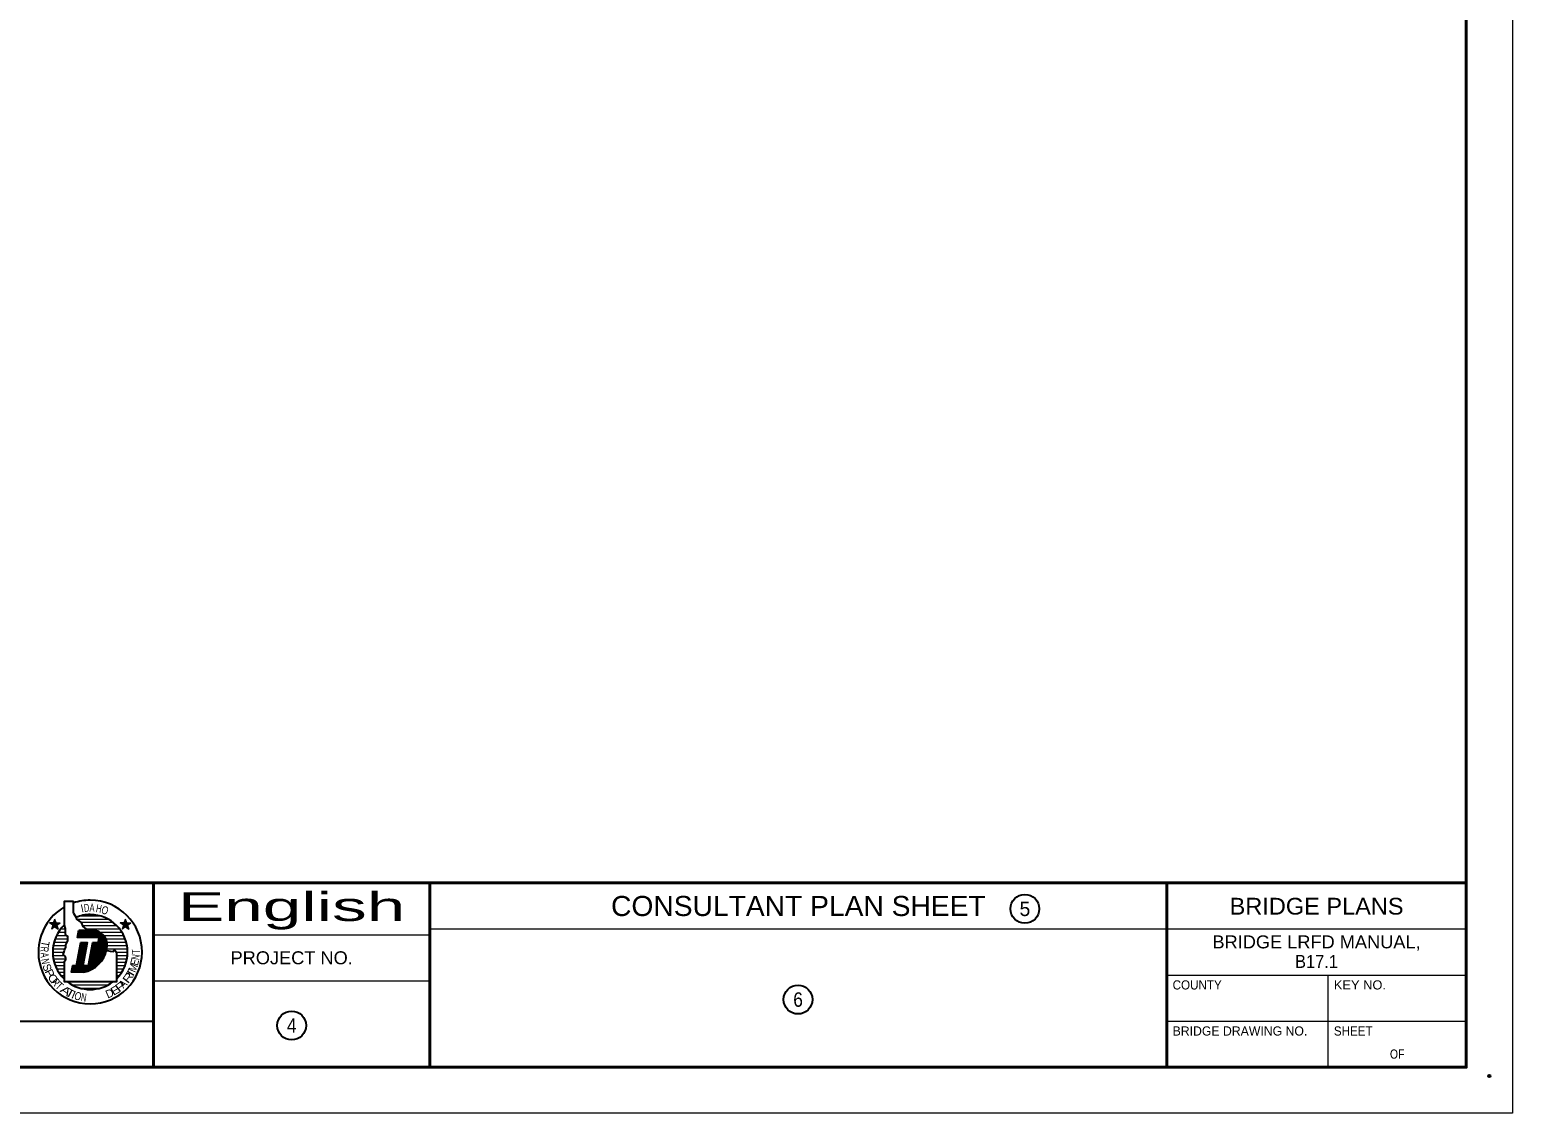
# Model space of a CAD drawing. Extents: x 0 to 34, y 0 to 23.5.
# Drawn here: x 17.91 to 34, y 0 to 11.76 of the extents above; entities that cross this region are included whole.
import ezdxf
from ezdxf.enums import TextEntityAlignment as Align

# ---------------------------------------------------------------- set-up
doc = ezdxf.new("R2010")
doc.units = 0
doc.header["$LTSCALE"] = 0.05
doc.header["$PDMODE"] = 32
doc.header["$PDSIZE"] = 0.025
doc.layers.add('49', color=7, linetype='Continuous')
doc.layers.add('50', color=7, linetype='Continuous', lineweight=13)
doc.layers.add('54', color=7, linetype='Continuous', lineweight=25)

msp = doc.modelspace()

# ---------------------------------------------------------------- linework, layer by layer
at = {"layer": '49'}
msp.add_point((33.75, 0.40625), dxfattribs=at)
at = {"layer": '50', "lineweight": 40}
for p, q in [((1.5, 2.5), (19.25, 2.5)), ((19.25, 0.5), (19.25, 2.5)), ((19.25, 2.5), (33.5, 2.5)), ((22.25, 0.5), (22.25, 2.5)), ((30.25, 0.5), (30.25, 2.5))]:
    msp.add_line(p, q, dxfattribs=at)
at = {"layer": '50', "lineweight": 25}
for p, q in [((18.38312, 2.17313), (18.38312, 2.30313)), ((18.43938, 1.90688), (18.45375, 1.98563)), ((18.44063, 1.98563), (18.6125, 1.98563)), ((18.455, 1.90688), (18.47, 1.98563)), ((18.47125, 1.90688), (18.48563, 1.98563)), ((18.48688, 1.90688), (18.50188, 1.98563)), ((18.5025, 1.90688), (18.5175, 1.98563)), ((18.51875, 1.90688), (18.53313, 1.98563)), ((18.53438, 1.90688), (18.54938, 1.98563)), ((18.55063, 1.90688), (18.565, 1.98563)), ((18.56625, 1.90688), (18.58125, 1.98563)), ((18.5825, 1.90688), (18.59688, 1.98563)), ((18.59812, 1.90688), (18.61313, 1.98563)), ((18.59938, 1.57438), (18.67188, 1.96188)), ((18.61375, 1.90688), (18.62813, 1.98125)), ((18.6175, 1.58563), (18.68625, 1.95188)), ((18.63, 1.90688), (18.64313, 1.97688)), ((18.63625, 1.60063), (18.69937, 1.93875)), ((18.64563, 1.90688), (18.6575, 1.97)), ((18.41625, 1.53188), (18.47687, 1.855)), ((18.4325, 1.53188), (18.49313, 1.855)), ((18.44813, 1.53188), (18.50875, 1.855)), ((18.46438, 1.53188), (18.525, 1.855)), ((18.54688, 1.5475), (18.60438, 1.855)), ((18.56375, 1.555), (18.62, 1.855)), ((18.58125, 1.56313), (18.63625, 1.855)), ((18.65563, 1.61875), (18.7125, 1.92438)), ((18.67563, 1.64), (18.725, 1.90625)), ((18.69688, 1.66875), (18.73688, 1.88188)), ((18.72188, 1.7175), (18.74563, 1.845)), ((18.36875, 1.53188), (18.3825, 1.605)), ((18.385, 1.53188), (18.39875, 1.605)), ((18.40063, 1.53188), (18.41437, 1.605)), ((18.48, 1.53188), (18.49375, 1.605)), ((18.49625, 1.5325), (18.51, 1.605)), ((18.51313, 1.53687), (18.52563, 1.605)), ((18.53, 1.54188), (18.54125, 1.605)), ((14, 1), (19.25, 1))]:
    msp.add_line(p, q, dxfattribs=at)
at = {"layer": '50'}
for p, q in [((18.16563, 2.06563), (18.17938, 2.10688)), ((18.17938, 2.02375), (18.17938, 2.10688)), ((18.19313, 2.06563), (18.17938, 2.10688)), ((18.41688, 2.10813), (18.75062, 2.10813)), ((18.465, 2.14438), (18.65813, 2.14438)), ((18.93188, 2.06563), (18.94562, 2.10688)), ((18.94562, 2.02375), (18.94562, 2.10688)), ((18.95938, 2.06563), (18.94562, 2.10688)), ((18.20125, 2.04), (18.1225, 2.06563)), ((18.16563, 2.06563), (18.1225, 2.06563)), ((18.1575, 2.04), (18.1225, 2.06563)), ((18.19313, 2.06563), (18.14375, 1.99813)), ((18.1575, 2.04), (18.14375, 1.99813)), ((18.17938, 2.02375), (18.14375, 1.99813)), ((18.1575, 2.04), (18.23688, 2.06563)), ((18.16563, 2.06563), (18.215, 1.99813)), ((18.17938, 2.02375), (18.215, 1.99813)), ((18.19313, 2.06563), (18.23688, 2.06563)), ((18.20125, 2.04), (18.23688, 2.06563)), ((18.20125, 2.04), (18.215, 1.99813)), ((18.21688, 1.96438), (18.2925, 1.96438)), ((18.24188, 2.00063), (18.29375, 2.00063)), ((18.27438, 2.03625), (18.28625, 2.03625)), ((18.465, 2.0725), (18.80688, 2.0725)), ((18.47875, 2.03625), (18.85063, 2.03625)), ((18.51562, 2.00063), (18.8825, 2.00063)), ((18.66875, 1.96438), (18.9075, 1.96438)), ((18.9675, 2.04), (18.88813, 2.06563)), ((18.92375, 2.04), (18.88813, 2.06563)), ((18.93188, 2.06563), (18.88813, 2.06563)), ((18.95938, 2.06563), (18.91, 1.99813)), ((18.92375, 2.04), (18.91, 1.99813)), ((18.94562, 2.02375), (18.91, 1.99813)), ((18.92375, 2.04), (19.0025, 2.06563)), ((18.93188, 2.06563), (18.98125, 1.99813)), ((18.94562, 2.02375), (18.98125, 1.99813)), ((18.95938, 2.06563), (19.0025, 2.06563)), ((18.9675, 2.04), (19.0025, 2.06563)), ((18.9675, 2.04), (18.98125, 1.99813)), ((19.25, 1.9375), (22.25, 1.9375)), ((22.25, 2), (30.25, 2)), ((30.25, 2), (33.5, 2)), ((18.1575, 1.78438), (18.29063, 1.78438)), ((18.1625, 1.82063), (18.29813, 1.82063)), ((18.17063, 1.85625), (18.31125, 1.85625)), ((18.18125, 1.8925), (18.31875, 1.8925)), ((18.19688, 1.92813), (18.29813, 1.92813)), ((18.71, 1.92813), (18.9275, 1.92813)), ((18.7325, 1.8925), (18.94313, 1.8925)), ((18.7425, 1.78438), (18.9675, 1.78438)), ((18.74438, 1.85625), (18.95438, 1.85625)), ((18.7475, 1.82063), (18.9625, 1.82063)), ((18.15625, 1.74813), (18.2775, 1.74813)), ((18.15813, 1.7125), (18.28125, 1.7125)), ((18.16313, 1.67625), (18.29813, 1.67625)), ((18.17125, 1.64062), (18.28375, 1.64062)), ((18.845, 1.74813), (18.96875, 1.74813)), ((18.84688, 1.67625), (18.96188, 1.67625)), ((18.84688, 1.64062), (18.95375, 1.64062)), ((18.8475, 1.7125), (18.96688, 1.7125)), ((18.18375, 1.60438), (18.2825, 1.60438)), ((18.19937, 1.56812), (18.2825, 1.56812)), ((18.22, 1.5325), (18.28313, 1.5325)), ((18.24563, 1.49625), (18.2825, 1.49625)), ((18.2775, 1.46063), (18.28375, 1.46063)), ((18.84688, 1.60438), (18.94125, 1.60438)), ((18.84688, 1.56812), (18.925, 1.56812)), ((18.84688, 1.5325), (18.905, 1.5325)), ((18.84688, 1.49625), (18.88, 1.49625)), ((30.25, 1.5), (33.5, 1.5)), ((32, 0.5), (32, 1.5)), ((18.75062, 1.39125), (18.37188, 1.39125)), ((18.65875, 1.35563), (18.4675, 1.35563)), ((19.25, 1.4375), (22.25, 1.4375)), ((30.25, 1), (33.5, 1))]:
    msp.add_line(p, q, dxfattribs=at)
msp.add_lwpolyline([(0, 22), (34, 22), (34, 0), (0, 0)], close=True, dxfattribs=at)
at = {"layer": '50', "lineweight": 40}
msp.add_lwpolyline([(1.5, 21.5), (33.5, 21.5), (33.5, 0.5), (1.5, 0.5)], close=True, dxfattribs=at)
at = {"layer": '50', "lineweight": 25}
for points in [[(18.74063, 1.7775), (18.74813, 1.76625), (18.77938, 1.76125), (18.81063, 1.75625), (18.82625, 1.77688), (18.84688, 1.74563), (18.84688, 1.4275), (18.28438, 1.4275), (18.28438, 1.65188), (18.3, 1.6675), (18.3, 1.68313), (18.29438, 1.69375), (18.28438, 1.70938), (18.26875, 1.725), (18.27875, 1.75063), (18.28438, 1.77188), (18.3, 1.80313), (18.3, 1.82875), (18.31, 1.85), (18.32062, 1.87563), (18.32062, 1.89125), (18.32062, 1.9175), (18.3, 1.92813), (18.29438, 1.94875), (18.29438, 1.975), (18.29438, 2.00625), (18.28438, 2.0425), (18.28438, 2.30313), (18.38312, 2.30313)], [(18.38312, 2.17313), (18.40938, 2.12625), (18.41437, 2.105), (18.46625, 2.06875), (18.4825, 2.02687), (18.53438, 1.98563)], [(18.4925, 1.53188), (18.35938, 1.53188), (18.37313, 1.605), (18.41437, 1.605), (18.46125, 1.855), (18.53, 1.855), (18.48313, 1.605), (18.54375, 1.605), (18.59063, 1.855), (18.65188, 1.855), (18.66125, 1.90688), (18.425, 1.90688), (18.44063, 1.98563)]]:
    msp.add_lwpolyline(points, dxfattribs=at)
for centre, radius, start, end in [((18.5625, 1.75), 0.5625, 90, 108.596), ((18.5625, 1.75), 0.5625, 0, 90), ((18.5625, 1.75), 0.5625, 119.63312, 180), ((18.5625, 1.75), 0.40625, 90, 112.14518), ((18.5625, 1.75), 0.40625, 0, 90), ((18.5625, 1.75), 0.40625, 133.19257, 180), ((18.58325, 1.82412), 0.16413, 343.49805, 79.73615), ((18.43491, 1.83819), 0.31168, 280.64795, 348.77185), ((18.5625, 1.75), 0.5625, 180, 270), ((18.5625, 1.75), 0.40625, 180.26444, 226.79463), ((18.5625, 1.75), 0.5625, 270, 0), ((18.5625, 1.75), 0.40625, 314.427, 0), ((18.5625, 1.75), 0.40625, 232.5658, 270), ((18.5625, 1.75), 0.40625, 270, 307.45359)]:
    msp.add_arc(centre, radius, start, end, dxfattribs=at)
at = {"layer": '54'}
for centre in [(28.70839, 2.21875), (26.24589, 1.23437), (20.74917, 0.95312)]:
    msp.add_circle(centre, 0.15625, dxfattribs=at)

# ---------------------------------------------------------------- texts
at = {"layer": '50'}
for s, height, width, p in [('English', 0.3125, 1.8, (20.74938, 2.08688)), ('CONSULTANT PLAN SHEET', 0.2181, 1.05, (26.2499, 2.14062)), ('BRIDGE PLANS', 0.1819, 1.05, (31.875, 2.15625)), ('BRIDGE LRFD MANUAL,', 0.1406, 1.05, (31.8744, 1.79)), ('PROJECT NO.', 0.1406, 1.05, (20.74969, 1.6175)), ('B17.1', 0.1406, 0.95, (31.87438, 1.5775)), ('OF', 0.09938, 0.85, (32.74969, 0.59375))]:
    msp.add_text(s, height=height, dxfattribs=dict(at, width=width)).set_placement(p, align=Align.CENTER)
for s, height, rotation, width, p in [('I', 0.08687, 11.952, 0.85, (18.48482, 2.18087)), ('D', 0.08688, 5.212, 0.6, (18.5273, 2.18675)), ('A', 0.08687, 357.872, 0.65, (18.58159, 2.18721)), ('H', 0.08688, 349.632, 0.65, (18.64937, 2.17872)), ('O', 0.08688, 342.192, 0.8, (18.70968, 2.16178)), ('R', 0.08687, 266.028, 0.6, (18.02448, 1.78205)), ('T', 0.08688, 259.426, 0.9, (18.03234, 1.84461)), ('T', 0.08687, 90.493, 0.7, (19.10167, 1.75319)), ('A', 0.08688, 273.764, 0.7, (18.02485, 1.71439)), ('N', 0.08686, 280.376, 0.7, (18.03424, 1.64129)), ('S', 0.08688, 287.928, 0.95, (18.05428, 1.56926)), ('M', 0.08688, 67.714, 0.9, (19.06745, 1.56168)), ('E', 0.08688, 75.61, 0.85, (19.08766, 1.62918)), ('N', 0.08688, 83.193, 0.65, (19.09828, 1.69061)), ('P', 0.08688, 295.498, 1.1, (18.08423, 1.50162)), ('O', 0.08688, 302.645, 1.15, (18.12327, 1.43684)), ('R', 0.08688, 309.908, 0.85, (18.15627, 1.39557)), ('R', 0.08686, 52.334, 1.35, (19.00798, 1.4456)), ('T', 0.08688, 59.036, 1.4, (19.03923, 1.49747)), ('T', 0.08688, 317.121, 0.85, (18.19888, 1.3514)), ('A', 0.08688, 324.638, 1.4, (18.27236, 1.29423)), ('T', 0.08688, 331.75, 1.35, (18.32559, 1.26473)), ('O', 0.08688, 343.329, 0.8, (18.41741, 1.23017)), ('N', 0.08688, 351.66, 0.7, (18.48729, 1.21582)), ('E', 0.08688, 30.548, 1.25, (18.8568, 1.29805)), ('P', 0.08688, 37.666, 1.45, (18.91747, 1.3436)), ('A', 0.08688, 45, 0.85, (18.94835, 1.37335))]:
    msp.add_text(s, height=height, rotation=rotation, dxfattribs=dict(at, width=width)).set_placement(p, align=Align.CENTER)
for s, rotation, p in [('I', 337.021, (18.36632, 1.24656)), ('D', 22.989, (18.79082, 1.26162))]:
    msp.add_text(s, height=0.08688, rotation=rotation, dxfattribs=at).set_placement(p, align=Align.CENTER)
for s, width, p in [('COUNTY', 0.95, (30.3125, 1.34375)), ('KEY NO.', 1.05, (32.0625, 1.34375)), ('SHEET', 0.95, (32.0625, 0.84375))]:
    msp.add_text(s, height=0.09938, dxfattribs=dict(at, width=width)).set_placement(p)
msp.add_text('BRIDGE DRAWING NO.', height=0.09938, dxfattribs=at).set_placement((30.3125, 0.84375))
at = {"layer": '54'}
msp.add_text('5', height=0.1563, dxfattribs=at).set_placement((28.70911, 2.14062), align=Align.CENTER)
at = {"layer": '54', "width": 0.9}
for s, p in [('6', (26.24659, 1.15625)), ('4', (20.74987, 0.875))]:
    msp.add_text(s, height=0.1563, dxfattribs=at).set_placement(p, align=Align.CENTER)

doc.saveas('drawing.dxf')
